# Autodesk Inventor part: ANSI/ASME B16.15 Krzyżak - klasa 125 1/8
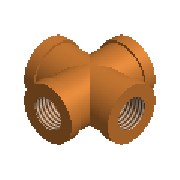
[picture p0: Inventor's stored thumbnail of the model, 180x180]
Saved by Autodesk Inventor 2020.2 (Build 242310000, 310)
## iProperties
Manager: www.cadconsulting.pl
Company: Fabian Stasiak CAD Consulting
IsCustomPart: 0
Created: 2014-02
Part Number: ANSI/ASME B16.15 Krzyżak - klasa 125 1/8
Material: Brąz, odlew
Description: Krzyżak odlewany z brązu, gwintowany - klasa 125
Document SubType Name: Modeling
Standard: ANSI/ASME B16.15
Designer: F.Stasiak
Standard Revision: 1985
Standards Organization: ANSI
Language: pl-PL
Size Designation: 1/8
Categories: <MemberInstance><Categories><Category DisplayName="Rury cienko- i grubościenne" InternalName="4347fa0f-2144-441d-94cd-e3e15c92b736" Mnemonic="TUBEANDPIPE"><Cate
Density: 1 g/cm^3
Appearance: Brąz - satynowy
Catalog Web Link: www.expertbooks.pl
NAME: PIPING: ANSI/ASME B16.15 Cross - Class 125
DATA: <meta><inlinegroups number="2" deflen="3.6068"></inlinegroups><connections number="4"></connections><angles><a>1.5707963267949</a><a>3.14159265358979</a><a>3.14
Author: F.Stasiak
Subject: Zbiór ćwiczeń. Autodesk Inventor 2020. Kurs Professional
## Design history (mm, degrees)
sketch "Sketch1"
  geometry: L1 (0, 8.509)-(3.556, 8.509); L2 (3.556, 8.509)-(3.556, 7.62); L3 (23.876, 7.62)-(23.876, 8.509); L4 (23.876, 8.509)-(27.432, 8.509); L5 (27.432, 8.509)-(27.432, 4.368); L6 (27.432, 4.368)-(27.432, 0); L7 (27.432, 0)-(0, 0); L8 (0, 0)-(0, 4.368); L9 (0, 4.368)-(6.35, 4.17); L10 (6.35, 4.17)-(6.35, 5.588); L11 (27.432, 4.368)-(21.082, 4.17); L12 (21.082, 4.17)-(21.082, 5.588); L13 (0, 4.368)-(0, 8.509); L14 (3.556, 8.509)-(13.716, 8.509); L15 (13.716, 8.509)-(23.876, 8.509); L16 (13.716, 8.509)-(13.716, 0); L17 (3.556, 7.62)-(13.716, 7.62); L18 (13.716, 7.62)-(23.876, 7.62); L19 (6.35, 5.588)-(13.716, 5.588); L20 (13.716, 5.588)-(21.082, 5.588)
  constraints: 40 end point, 5 perpendicular, 4 collinear, 3 parallel, 2 point on line, 1 horizontal, 1 midpoint, 8 other
  dimensions: "d0" = 8.73684 diameter of L8.end L7 (= MD); "d1" = 17.018 diameter of L1 L7 (= H); "d2" = 3.556 distance of L1.start L1.end (= E1); "d3" = 13.716 distance of L14.end L1.start (= A); "d4" = 6.35 horizontal distance of L9.end L8.end (= B); "d5" = 11.176 diameter of L19 L7 (= F1); "d6" = 2.032 distance between parallel lines of L19 L17 (= G); "d7" = 1.78991 deg angle of L7 L9
revolve "Revolve1" stored, may be unused: angle "d11" = 90 deg
workplane "Work Plane1"
sketch "Sketch2"
  geometry: L1 (0, 8.509)-(0, -8.509) reference; L2 (27.432, 8.509)-(27.432, -8.509) reference; L3 (27.432, 4.368)-(27.432, -4.368) reference; L4 (0, 0)-(27.432, 0); C1 r 4.368 at (13.716, 0); C2 r 7.62 at (13.716, 0); C3 r 8.509 at (13.716, 0)
  constraints: 3 centre point, 3 midpoint, 2 coincident, 2 concentric, 2 end point
  dimensions: "d9" = 17.018 diameter of C3 (= H); "d10" = 15.24 diameter of C2 (= F1 + 2 x G); "d12" = 8.73684 diameter of C1 (= MD)
  node "Projected Loop1"
extrude "Extrude1" join sketch "Sketch2" taper "d13" = 0 deg; stored distance "d16" = 25.4
extrude "Extrude2" cut sketch "Sketch2" distance "d14" = 13.716 (= A); taper "d15" = -1.78991 deg
extrude "Extrude3" join sketch "Sketch2" distance "d17" = 3.556 (= E1); taper "d18" = 0 deg
sketch "Sketch3"
  geometry: L1 (27.432, 8.509)-(27.432, -8.509) reference; L2 (0, 8.509)-(0, -8.509) reference; L3 (27.432, 0)-(0, 0); C1 r 5.588 at (13.716, 0)
  constraints: 3 midpoint, 2 end point, 1 centre point
  dimensions: "d19" = 11.176 diameter of C1 (= F1)
workplane "Work Plane2"
sketch "Sketch4"
  geometry: L1 (0, 8.509)-(0, -8.509) reference; L2 (27.432, 8.509)-(27.432, -8.509) reference; L3 (27.432, 0)-(0, 0); C1 r 4.368 at (13.716, 0); C2 r 7.62 at (13.716, 0); C3 r 8.509 at (13.716, 0)
  constraints: 3 centre point, 3 midpoint, 2 coincident, 2 concentric, 2 end point, 1 horizontal
  dimensions: "d21" = 8.73684 diameter of C1 (= MD); "d22" = 17.018 diameter of C3 (= H); "d23" = 15.24 diameter of C2 (= F1 + 2 x G)
extrude "Extrude4" join sketch "Sketch4" taper "d24" = 0 deg; stored distance "d45" = 25.4
extrude "Extrude5" join sketch "Sketch4" distance "d25" = 3.556 (= E1); taper "d26" = 0 deg
extrude "Extrude6" cut sketch "Sketch4" distance "d27" = 13.716 (= A); taper "d28" = -1.78991 deg
extrude "Extrude7" cut sketch "Sketch3" stored distance "d29" = 14.732 (= -2 x B + 2 x A); taper "d30" = 0 deg
workaxis "Work Axis1"
workpoint "Work Point1"
workpoint "Work Point2"
workaxis "Work Axis2"
workpoint "Work Point3"
workpoint "Work Point4"
workaxis "Work Axis3"
workpoint "Work Point5"
workpoint "Work Point6"
workaxis "Work Axis4"
workpoint "Work Point7"
workpoint "Work Point8"
body "Solid1"
feature "Gwint1" dims "d57" = 25.4, "d58" = 0
feature "Gwint2" dims "d59" = 25.4, "d60" = 0
feature "Gwint3" dims "d61" = 25.4, "d62" = 0
feature "Gwint4" dims "d63" = 25.4, "d64" = 0
other parameters: "A" = 13.716 [user parameter; used in 6 equation terms], "B" = 6.35 [user parameter; used in 2 equation terms], "E1" = 3.556 [user parameter; used in 3 equation terms], "F1" = 11.176 [user parameter; used in 4 equation terms], "G" = 2.032 [user parameter; used in 3 equation terms], "H" = 17.018 [user parameter; used in 3 equation terms], "MD" = 8.73684 [user parameter; used in 3 equation terms], "d8" = 13.716 (= A), "d20" = -13.716 (= -A), "Size_Designation" = 1.25 [user parameter]
